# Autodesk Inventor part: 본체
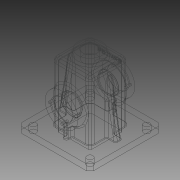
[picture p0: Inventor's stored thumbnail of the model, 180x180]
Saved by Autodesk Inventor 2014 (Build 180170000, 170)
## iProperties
Created: 2017-08
Part Number: 본체
Material: 알루미늄 6061
Document SubType Name: Modeling
Designer: user
Density: 2.71 g/cm^3
Appearance: 알루미늄 - 평지
Mass: 798.825 g
Surface Area: 901.718 cm^2
Volume: 294.769 cm^3
Author: user
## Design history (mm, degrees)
sketch "스케치1"
  geometry: L1 (32.5, -32.5)-(-32.5, -32.5); L2 (-32.5, -32.5)-(-32.5, 32.5); L3 (-32.5, 32.5)-(32.5, 32.5); L4 (32.5, 32.5)-(32.5, -32.5); L5 (32.5, -32.5)-(-32.5, 32.5); L6 (-32.5, -32.5)-(32.5, 32.5); 1 further point
  constraints: 12 end point, 2 midpoint, 2 parallel, 2 perpendicular, 1 horizontal
  dimensions: "d0" = 65 distance of L2.end L3.end
extrude "돌출1" new body sketch "스케치1" distance "d1" = 110; taper "d2" = 0 deg
fillet "모깎기1" dims "d3" = 8
fillet "모깎기2" dims "d4" = 8
feature "쉘1" dims "d5" = 5
node "작업 평면1"
sketch "스케치3"
  geometry: L1 (24.5, 0)-(-24.5, 0) reference; C1 r 27.5 at (0, 55); 2 further points
  constraints: 1 centre point, 1 midpoint, 1 vertical alignment
  dimensions: "d9" = 55 distance of point (0, 0) C1.centre; "d10" = 55 diameter of C1
extrude "돌출2" join sketch "스케치3" stored distance "d11" = 10; taper "d12" = 0 deg
hole "구멍1" diameter "d15" = 30; stored, may be unused: countersink angle "d19" = 90 deg, drill point angle "d21" = 0 deg; dims "d13" = 10, "d14" = 10, "d16" = 6, "d17" = 35, "d18" = 17, "d20" = 8
sketch "스케치4"
  geometry: C1 r 17.5 at (0, 0) reference; 2 further points
  constraints: 1 vertical alignment
  dimensions: "d22" = 21 distance of point (0, 21) C1.centre
hole "구멍2" sketch "스케치4" at (0, 21) diameter "d23" = 3.242; stored, may be unused: countersink angle "d27" = 90 deg, drill point angle "d29" = 118 deg; dims "d24" = 8, "d25" = 35, "d26" = 17, "d28" = 10
node "작업 평면2"
sketch "스케치5"
  geometry: C1 r 20 at (0, 0); 1 further point
  constraints: 1 centre point, 1 coincident
  dimensions: "d34" = 40 diameter of C1
extrude "돌출3" join sketch "스케치5" stored distance "d35" = 10; taper "d36" = 7 deg
hole "구멍3" diameter "d39" = 22.835; stored, may be unused: countersink angle "d43" = 90 deg, drill point angle "d45" = 0 deg; dims "d37" = 10, "d38" = 10, "d40" = 8, "d41" = 35, "d42" = 17, "d44" = 10
sketch "스케치6"
  geometry: L1 (24.5, 32.5)-(-24.5, 32.5) reference; L2 (-32.5, 24.5)-(-32.5, -24.5) reference; L3 (-24.5, -32.5)-(24.5, -32.5) reference; L4 (32.5, -24.5)-(32.5, 24.5) reference; L5 (60, -60)-(-60, -60); L6 (-60, -60)-(-60, 60); L7 (-60, 60)-(60, 60); L8 (60, 60)-(60, -60); L9 (60, -60)-(-60, 60); L10 (-60, -60)-(60, 60); L11 (-60, 54.343)-(-54.343, 60); L12 (-60, -54.343)-(-54.343, -60); L13 (54.343, -60)-(60, -54.343); L14 (54.343, 60)-(60, 54.343); A1 r 8 centre (-24.5, 24.5) between (-24.5, 32.5) and (-32.5, 24.5) reference; A2 r 8 centre (-24.5, -24.5) between (-32.5, -24.5) and (-24.5, -32.5) reference; A3 r 8 centre (24.5, -24.5) between (24.5, -32.5) and (32.5, -24.5) reference; A4 r 8 centre (24.5, 24.5) between (32.5, 24.5) and (24.5, 32.5) reference; 1 further point
  constraints: 20 end point, 8 perpendicular, 8 point on line, 3 parallel, 2 midpoint, 1 horizontal
  dimensions: "d46" = 120 distance of L6.end L7.end; "d47" = 8 distance of L11.start L11.end
extrude "돌출4" join sketch "스케치6" distance "d48" = 10; taper "d49" = 0 deg
sketch "스케치7"
  geometry: L1 (-32.5, 10)-(-32.5, 102) reference; L2 (54.343, 10)-(-54.343, 10) reference; L3 (-48, 10)-(-32.5, 97.905); L4 (-60, 0)-(-60, 10) reference; 1 further point
  constraints: 2 end point, 2 point on line
  dimensions: "d50" = 10 deg angle of L3 L4; "d51" = 12 distance of L4.end L3.start
feature "리브1" sketch "스케치7" dims "d52" = 1, "d53" = 10, "d54" = 0, "d55" = 0, "d56" = 1, "d57" = 1
sketch "스케치8"
  geometry: L1 (-47.5, 27.5)-(-32.5, 27.5) reference; L2 (54.343, 10)-(-54.343, 10) reference; L3 (-27.5, 0)-(-27.5, 102) reference; L4 (-42.5, 27.5)-(-42.5, 10); 1 further point
  constraints: 2 end point, 2 point on line, 1 perpendicular
  dimensions: "d58" = 15 distance between parallel lines of L3 L4
feature "리브2" sketch "스케치8" dims "d59" = 1, "d60" = 6, "d61" = 0, "d62" = 0, "d63" = 1, "d64" = 1
sketch "스케치9"
  geometry: L1 (54.343, 60)-(-54.343, 60) reference; 3 further points
  constraints: 1 vertical alignment
  dimensions: "d65" = 47.5 horizontal distance of point (-47.5, 47.5) point (0, 0); "d66" = 95 distance of point (-47.5, -47.5) point (-47.5, 47.5); "d67" = 12.5 distance from line of L1 point (-47.5, 47.5)
hole "구멍4" sketch "스케치9" at (-47.5, 47.5), (-47.5, -47.5) diameter "d68" = 10; stored, may be unused: countersink angle "d72" = 90 deg, drill point angle "d74" = 0 deg; dims "d69" = 8, "d70" = 35, "d71" = 17, "d73" = 10
chamfer "모따기1" distance "d75" = 1; stored, may be unused: second distance "d76" = 2, angle "d77" = 45 deg
chamfer "모따기2" distance "d78" = 1; stored, may be unused: second distance "d79" = 2, angle "d80" = 45 deg
chamfer "모따기3" distance "d81" = 1; stored, may be unused: second distance "d82" = 2, angle "d83" = 45 deg
fillet "모깎기3" dims "d84" = 3
fillet "모깎기4" dims "d85" = 3
fillet "모깎기5" dims "d86" = 3
fillet "모깎기6" dims "d87" = 3
fillet "모깎기7" dims "d88" = 3
fillet "모깎기8" dims "d89" = 3
fillet "모깎기9" dims "d90" = 3
fillet "모깎기10" dims "d91" = 1
sketch "스케치10"
  geometry: L1 (44.5, -18)-(4.5, -18) reference; L2 (57, 0)-(57, 91) reference; 2 further points
  constraints: 1 other
  dimensions: "d92" = 26 distance from line of L1 point (24.5, 8); "d93" = 32.5 distance from line of L2 point (24.5, 8)
feature "엠보싱1" sketch "스케치10" dims "d8" = -47.5, "d94" = 0.5, "d95" = 0
fillet "모깎기11" dims "d96" = 0.3
fillet "모깎기12" dims "d97" = 0.3
node "솔리드1"
pattern_circular "원형 패턴1" dims angle "d31" = 360 deg
mirror "대칭1"
mirror "대칭2"
mirror "대칭3"
mirror "대칭4"
node "작업 평면3"
